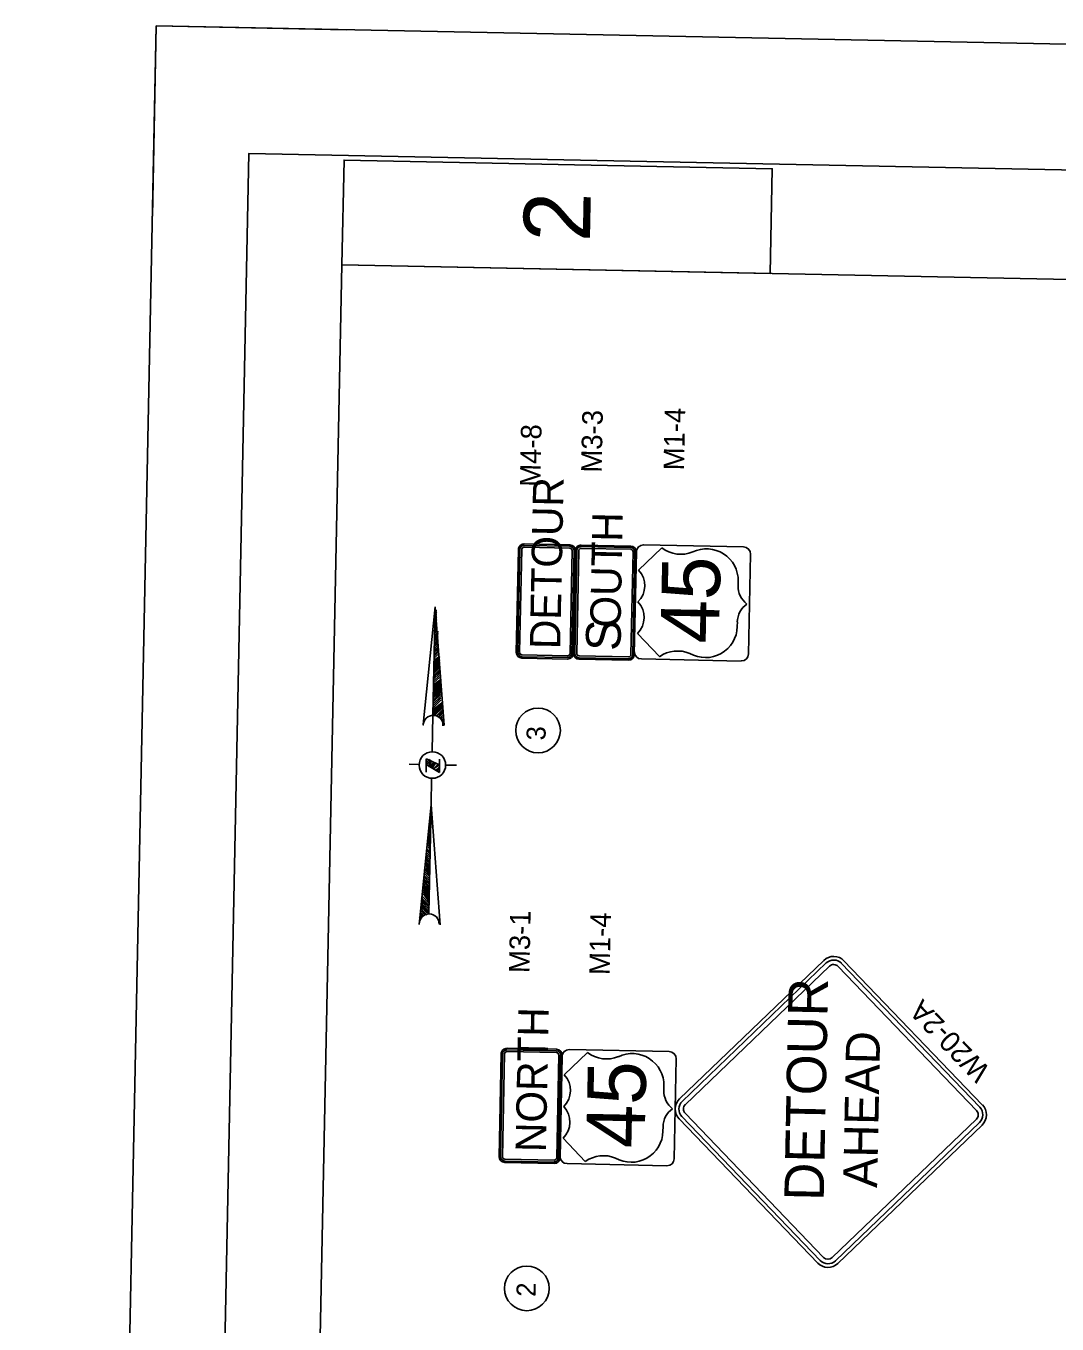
# Model space of a CAD drawing. Extents: x 311409 to 379449, y 121539 to 224848.
# Drawn here: x 311409 to 327657, y 204381 to 224848 of the extents above; entities that cross this region are included whole.
import ezdxf

# ---------------------------------------------------------------- set-up
doc = ezdxf.new("R2010")
doc.units = 0
for name, color, linetype in [('CA-TBLK', 7, 'Continuous'), ('CA-TEXT', 7, 'Continuous'), ('P_RDWY_Text', 7, 'Continuous'), ('P_SGN_Cell', 7, 'Continuous'), ('PLT_Sheet_Border', 7, 'Continuous'), ('PLT_Sheet_Info', 7, 'Continuous')]:
    doc.layers.add(name, color=color, linetype=linetype)

msp = doc.modelspace()

# ---------------------------------------------------------------- linework, layer by layer
at = {"layer": 'CA-TBLK'}
for p, q in [((317669, 213832), (317856, 215689)), ((317822, 213979), (317856, 215689)), ((317883, 215538), (317853, 215539)), ((317853, 215509), (317883, 215538)), ((317854, 215599), (317884, 215598)), ((317884, 215598), (317854, 215569)), ((317854, 215569), (317884, 215568)), ((317855, 215629), (317885, 215628)), ((317885, 215628), (317855, 215629)), ((317999, 213826), (317856, 215689)), ((317856, 215689), (317856, 215689)), ((317856, 215689), (317856, 215689)), ((317856, 215659), (317856, 215659)), ((317848, 215299), (317879, 215328)), ((317879, 215328), (317848, 215299)), ((317849, 215329), (317880, 215358)), ((317881, 215418), (317850, 215389)), ((317880, 215388), (317850, 215359)), ((317850, 215359), (317880, 215388)), ((317882, 215478), (317851, 215449)), ((317851, 215449), (317881, 215448)), ((317881, 215448), (317851, 215419)), ((317851, 215419), (317881, 215418)), ((317852, 215479), (317883, 215508)), ((317883, 215508), (317853, 215509)), ((317844, 215089), (317905, 215148)), ((317905, 215118), (317844, 215089)), ((317844, 215059), (317905, 215118)), ((317907, 215208), (317845, 215149)), ((317845, 215119), (317906, 215178)), ((317905, 215148), (317845, 215119)), ((317907, 215238), (317846, 215179)), ((317846, 215179), (317907, 215208)), ((317847, 215239), (317908, 215298)), ((317908, 215268), (317847, 215239)), ((317847, 215209), (317907, 215238)), ((317878, 215298), (317848, 215269)), ((317931, 214907), (317839, 214819)), ((317839, 214849), (317931, 214907)), ((317901, 214938), (317840, 214879)), ((317840, 214879), (317901, 214938)), ((317902, 214998), (317841, 214939)), ((317841, 214939), (317902, 214998)), ((317902, 214968), (317841, 214909)), ((317842, 214999), (317904, 215058)), ((317842, 214969), (317903, 215028)), ((317903, 215028), (317842, 214999)), ((317904, 215088), (317843, 215029)), ((317927, 214727), (317835, 214639)), ((317835, 214609), (317926, 214697)), ((317836, 214699), (317928, 214757)), ((317928, 214757), (317836, 214669)), ((317836, 214669), (317927, 214727)), ((317837, 214729), (317929, 214817)), ((317928, 214787), (317837, 214729)), ((317838, 214759), (317929, 214847)), ((317929, 214847), (317838, 214789)), ((317929, 214817), (317838, 214759)), ((317839, 214819), (317930, 214877)), ((317830, 214399), (317952, 214487)), ((317952, 214487), (317830, 214399)), ((317953, 214547), (317831, 214429)), ((317831, 214429), (317953, 214517)), ((317924, 214577), (317832, 214489)), ((317832, 214489), (317924, 214577)), ((317832, 214459), (317953, 214547)), ((317833, 214549), (317925, 214637)), ((317925, 214637), (317833, 214549)), ((317925, 214607), (317833, 214519)), ((317834, 214579), (317926, 214667)), ((317926, 214667), (317835, 214609)), ((317826, 214189), (317948, 214307)), ((317950, 214367), (317827, 214249)), ((317827, 214219), (317949, 214337)), ((317948, 214307), (317827, 214219)), ((317950, 214397), (317828, 214279)), ((317828, 214279), (317950, 214367)), ((317829, 214339), (317951, 214457)), ((317951, 214427), (317829, 214339)), ((317829, 214309), (317950, 214397)), ((317951, 214457), (317830, 214369)), ((317822, 214009), (317975, 214126)), ((317975, 214126), (317822, 214009)), ((317974, 214096), (317822, 213979)), ((317976, 214186), (317823, 214039)), ((317823, 214039), (317975, 214156)), ((317947, 214217), (317824, 214099)), ((317824, 214099), (317947, 214217)), ((317824, 214069), (317976, 214186)), ((317825, 214159), (317948, 214277)), ((317948, 214277), (317825, 214159)), ((317947, 214247), (317825, 214129)), ((317852, 213979), (317974, 214096)), ((317822, 213979), (317810, 213409)), ((317974, 214066), (317882, 213978)), ((317882, 213978), (317973, 214036)), ((317973, 214036), (317911, 213947)), ((317972, 214006), (317911, 213947)), ((317911, 213947), (317972, 214006)), ((317941, 213947), (317972, 213976)), ((317971, 213946), (317941, 213917)), ((317941, 213917), (317971, 213946)), ((317970, 213886), (317971, 213916)), ((317970, 213886), (317970, 213886)), ((317971, 213916), (317971, 213916)), ((317969, 213856), (317969, 213856)), ((317969, 213856), (317969, 213856)), ((317969, 213826), (317999, 213826)), ((317718, 213291), (317714, 213081)), ((317777, 213260), (317716, 213201)), ((317716, 213201), (317777, 213260)), ((317716, 213201), (317807, 213259)), ((317717, 213261), (317748, 213291)), ((317748, 213291), (317717, 213261)), ((317778, 213290), (317717, 213231)), ((317718, 213291), (317718, 213291)), ((317926, 213197), (317718, 213291)), ((317807, 213259), (317746, 213171)), ((317928, 213287), (317924, 213077)), ((317596, 213204), (317446, 213207)), ((317716, 213201), (317924, 213077)), ((317746, 213171), (317837, 213229)), ((317837, 213229), (317776, 213170)), ((317776, 213170), (317867, 213228)), ((317805, 213139), (317867, 213228)), ((317867, 213228), (317806, 213169)), ((317835, 213139), (317896, 213198)), ((317896, 213198), (317835, 213139)), ((317926, 213197), (317835, 213139)), ((317864, 213108), (317926, 213167)), ((317926, 213167), (317864, 213108)), ((317894, 213108), (317925, 213137)), ((317925, 213137), (317894, 213108)), ((317924, 213077), (317924, 213107)), ((318016, 213195), (318196, 213191)), ((317802, 212989), (317793, 212569)), ((317605, 210683), (317793, 212569)), ((317759, 210860), (317793, 212569)), ((317790, 212419), (317791, 212449)), ((317791, 212449), (317791, 212449)), ((317792, 212509), (317792, 212509)), ((317792, 212479), (317792, 212479)), ((317792, 212479), (317792, 212479)), ((317935, 210676), (317793, 212569)), ((317793, 212569), (317793, 212569)), ((317793, 212539), (317793, 212539)), ((317793, 212539), (317793, 212539)), ((317757, 212240), (317786, 212210)), ((317787, 212270), (317788, 212300)), ((317787, 212270), (317787, 212240)), ((317787, 212240), (317787, 212270)), ((317788, 212300), (317789, 212330)), ((317788, 212300), (317788, 212300)), ((317790, 212389), (317789, 212360)), ((317789, 212360), (317789, 212330)), ((317789, 212360), (317789, 212360)), ((317790, 212419), (317790, 212419)), ((317790, 212389), (317790, 212389)), ((317753, 212060), (317783, 212030)), ((317784, 212090), (317754, 212120)), ((317754, 212120), (317784, 212090)), ((317783, 212030), (317754, 212090)), ((317754, 212090), (317783, 212060)), ((317784, 212120), (317755, 212150)), ((317786, 212210), (317756, 212210)), ((317756, 212210), (317786, 212180)), ((317756, 212180), (317784, 212120)), ((317785, 212150), (317756, 212180)), ((317719, 211851), (317778, 211790)), ((317778, 211820), (317719, 211851)), ((317720, 211881), (317778, 211820)), ((317779, 211850), (317750, 211910)), ((317750, 211910), (317779, 211850)), ((317751, 211970), (317780, 211910)), ((317780, 211910), (317751, 211970)), ((317780, 211880), (317751, 211940)), ((317752, 212000), (317781, 211940)), ((317781, 211970), (317752, 212000)), ((317753, 212030), (317781, 211970)), ((317782, 212000), (317753, 212030)), ((317715, 211671), (317774, 211580)), ((317774, 211610), (317715, 211671)), ((317774, 211580), (317715, 211641)), ((317715, 211641), (317773, 211550)), ((317716, 211701), (317775, 211640)), ((317776, 211700), (317717, 211761)), ((317717, 211761), (317776, 211700)), ((317775, 211640), (317717, 211731)), ((317717, 211731), (317775, 211670)), ((317718, 211821), (317777, 211760)), ((317777, 211760), (317718, 211821)), ((317777, 211730), (317718, 211791)), ((317681, 211461), (317769, 211370)), ((317769, 211370), (317681, 211461)), ((317769, 211340), (317681, 211432)), ((317682, 211521), (317771, 211430)), ((317682, 211491), (317770, 211400)), ((317770, 211400), (317682, 211491)), ((317771, 211460), (317683, 211551)), ((317713, 211551), (317771, 211460)), ((317772, 211520), (317714, 211611)), ((317772, 211490), (317714, 211581)), ((317714, 211581), (317772, 211520)), ((317764, 211100), (317676, 211222)), ((317676, 211222), (317765, 211130)), ((317765, 211130), (317677, 211252)), ((317678, 211312), (317766, 211190)), ((317766, 211220), (317678, 211312)), ((317678, 211282), (317765, 211160)), ((317766, 211190), (317678, 211282)), ((317767, 211250), (317679, 211372)), ((317679, 211372), (317768, 211280)), ((317679, 211342), (317767, 211250)), ((317680, 211402), (317768, 211310)), ((317768, 211310), (317680, 211402)), ((317759, 210860), (317642, 211012)), ((317642, 211012), (317760, 210890)), ((317761, 210950), (317643, 211072)), ((317760, 210920), (317643, 211042)), ((317643, 211042), (317760, 210920)), ((317644, 211102), (317761, 210950)), ((317761, 210980), (317644, 211102)), ((317645, 211132), (317762, 211010)), ((317762, 211010), (317645, 211132)), ((317675, 211162), (317763, 211040)), ((317763, 211070), (317676, 211192)), ((317676, 211192), (317763, 211070)), ((317608, 210803), (317637, 210772)), ((317638, 210832), (317668, 210802)), ((317638, 210802), (317638, 210832)), ((317668, 210802), (317639, 210862)), ((317639, 210862), (317668, 210832)), ((317640, 210922), (317698, 210831)), ((317728, 210830), (317640, 210922)), ((317698, 210831), (317640, 210892)), ((317641, 210952), (317729, 210860)), ((317759, 210860), (317641, 210952)), ((317642, 210982), (317759, 210860)), ((317606, 210713), (317606, 210713)), ((317607, 210773), (317637, 210772)), ((317637, 210772), (317607, 210773)), ((317607, 210743), (317607, 210743)), ((317607, 210743), (317607, 210743))]:
    msp.add_line(p, q, dxfattribs=at)
msp.add_circle((317813, 213195), 209, dxfattribs=at)
for centre, start, end in [((317826, 213821), 358.8468, 178.8468), ((317826, 213821), 178.84682431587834, 178.8468298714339), ((317763, 210691), 358.8468, 178.8468), ((317763, 210691), 358.84700764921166, 358.8470132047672)]:
    msp.add_arc(centre, 157, start, end, dxfattribs=at)
at = {"layer": 'CA-TEXT'}
for centre in [(319479, 213740), (319302, 204944)]:
    msp.add_circle(centre, 352, dxfattribs=at)
at = {"layer": 'P_RDWY_Text'}
msp.add_lwpolyline([(311409, 122868), (313463, 224848), (379449, 223519), (377396, 121539)], close=True, dxfattribs=at)
at = {"layer": 'P_SGN_Cell'}
for p, q in [((320036, 214955), (320068, 216576)), ((320058, 214955), (320091, 216575)), ((320088, 214955), (320121, 216574)), ((320159, 216611), (320939, 216596)), ((320160, 216664), (320940, 216648)), ((320160, 216641), (320940, 216626)), ((320976, 216557), (320943, 214938)), ((321006, 216557), (320973, 214937)), ((321028, 216556), (320996, 214937)), ((320996, 214982), (321028, 216556)), ((321429, 216618), (321064, 216268)), ((321143, 216666), (322718, 216635)), ((322828, 216520), (322812, 215733)), ((322828, 216520), (322828, 216520)), ((322631, 216022), (322633, 216093)), ((322812, 215733), (322796, 214945)), ((322618, 215379), (322620, 215451)), ((321044, 215268), (321394, 214904)), ((320125, 214917), (320905, 214901)), ((320124, 214887), (320904, 214871)), ((320124, 214864), (320904, 214848)), ((322681, 214835), (321107, 214867)), ((318865, 207020), (318898, 208641)), ((318888, 207021), (318920, 208640)), ((318918, 207020), (318950, 208640)), ((318989, 208706), (319769, 208691)), ((318989, 208676), (319768, 208661)), ((318990, 208729), (319770, 208713)), ((319805, 208622), (319773, 207003)), ((319835, 208622), (319803, 207002)), ((319858, 208621), (319825, 207002)), ((319826, 207024), (319857, 208599)), ((320258, 208661), (319893, 208311)), ((319972, 208709), (321547, 208677)), ((321657, 208563), (321641, 207775)), ((321657, 208563), (321657, 208563)), ((321460, 208065), (321462, 208136)), ((321641, 207775), (321625, 206988)), ((321447, 207422), (321449, 207493)), ((319873, 207311), (320223, 206946)), ((318953, 206929), (319733, 206914)), ((318954, 206982), (319734, 206966)), ((318954, 206952), (319734, 206936)), ((321510, 206878), (319936, 206910))]:
    msp.add_line(p, q, dxfattribs=at)
for points in [[(319169, 216592), (319136, 214973)], [(319191, 216592), (319158, 214972)], [(319221, 216591), (319188, 214972)], [(319979, 216614), (319259, 216628)], [(319980, 216666), (319260, 216681)], [(319980, 216644), (319260, 216658)], [(319983, 214956), (320016, 216575)], [(320013, 214955), (320046, 216575)], [(320036, 214955), (320068, 216574)], [(319225, 214933), (319945, 214919)], [(319225, 214903), (319944, 214889)], [(319224, 214881), (319944, 214866)], [(323982, 210115), (321710, 207933)], [(324021, 210074), (321750, 207892)], [(324071, 210022), (321799, 207840)], [(326388, 207750), (324206, 210021)], [(326439, 207799), (324258, 210070)], [(326480, 207839), (324299, 210110)], [(321704, 207615), (323886, 205343)], [(321745, 207655), (323927, 205383)], [(321796, 207704), (323978, 205432)], [(324115, 205430), (326387, 207612)], [(324164, 205378), (326436, 207560)], [(324204, 205337), (326476, 207519)]]:
    msp.add_lwpolyline(points, dxfattribs=at)
for centre, radius, start, end in [((319259, 216591), 90, 88.8468, 178.8468), ((319259, 216591), 67.5, 88.8468, 178.8468), ((319259, 216591), 37.5, 88.8468, 178.8468), ((319978, 216576), 37.5, 358.8468, 88.8468), ((319978, 216576), 90, 358.8468, 88.8468), ((319978, 216576), 67.5, 358.8468, 88.8468), ((320158, 216574), 90, 88.8462, 178.8462), ((320158, 216574), 67.5, 88.8462, 178.8462), ((320158, 216574), 37.5, 88.8462, 178.8462), ((320938, 216558), 37.5, 358.8462, 88.8462), ((320938, 216558), 90, 358.8462, 88.8462), ((320938, 216558), 67.5, 358.8462, 88.8462), ((321141, 216554), 112, 88.8462, 178.8462), ((321729, 217018), 500, 233.1143, 291.9873), ((322133, 216104), 500, 358.8462, 115.6928), ((322715, 216522), 112, 358.8462, 88.8462), ((320804, 216023), 357, 314.4191, 43.2734), ((322993, 216017), 362, 179.1885, 231.634), ((320794, 215523), 357, 314.4191, 43.2734), ((322981, 215441), 362, 126.0584, 178.5039), ((322118, 215389), 500, 240.0981, 358.8463), ((319226, 214971), 90, 178.8468, 268.8468), ((319226, 214971), 67.5, 178.8468, 268.8468), ((319226, 214971), 37.5, 178.8468, 268.8468), ((319226, 214971), 37.5, 178.8468, 186.1883), ((319946, 214956), 90, 268.8468, 358.8468), ((319946, 214956), 67.5, 268.8468, 358.8468), ((319946, 214956), 37.5, 268.8468, 358.8468), ((320126, 214954), 90, 179.6119, 268.8462), ((320126, 214954), 67.5, 178.8462, 268.8462), ((320126, 214954), 37.5, 178.8462, 268.8462), ((320906, 214938), 67.5, 268.8462, 358.8462), ((320906, 214938), 90, 268.8462, 358.8462), ((320906, 214938), 37.5, 268.8462, 358.8462), ((321109, 214979), 112, 178.8462, 268.8462), ((321679, 214493), 500, 67.7159, 124.7982), ((322684, 214948), 112, 268.8462, 358.8462), ((324138, 209953), 225, 43.8468, 133.8468), ((324138, 209953), 168, 43.8468, 133.8468), ((324138, 209953), 96.4, 43.8468, 133.8468), ((318988, 208639), 90, 88.8462, 178.8462), ((318988, 208639), 67.5, 88.8462, 178.8462), ((318988, 208639), 37.5, 88.8462, 178.8462), ((319768, 208623), 37.5, 358.8462, 88.8462), ((319768, 208623), 67.5, 358.8462, 88.8462), ((319768, 208623), 90, 358.8462, 88.8462), ((319970, 208597), 112, 88.8462, 178.8462), ((320558, 209061), 500, 233.1143, 291.9873), ((320962, 208146), 500, 358.8462, 115.6928), ((321544, 208565), 112, 358.8462, 88.8462), ((319633, 208066), 357, 314.4191, 43.2734), ((321822, 208060), 362, 179.1885, 231.634), ((319623, 207566), 357, 314.4191, 43.2734), ((321810, 207484), 362, 126.0584, 178.5039), ((321866, 207771), 225, 133.8449, 223.8468), ((321866, 207771), 168, 133.8449, 223.8468), ((321866, 207771), 96.4, 133.8449, 223.8468), ((326320, 207681), 96.4, 313.854, 44.4977), ((326320, 207681), 168, 313.854, 44.4977), ((326320, 207681), 225, 313.854, 44.4977), ((320947, 207432), 500, 240.0981, 358.8463), ((318955, 207019), 90, 179.6119, 268.8462), ((318955, 207019), 67.5, 178.8462, 268.8462), ((318955, 207019), 37.5, 178.8462, 268.8462), ((319735, 207004), 90, 268.8462, 358.8462), ((319735, 207004), 37.5, 268.8462, 358.8462), ((319735, 207004), 67.5, 268.8462, 358.8462), ((319938, 207022), 112, 178.8462, 268.8462), ((320509, 206536), 500, 67.7159, 124.7982), ((321513, 206990), 112, 268.8462, 358.8462), ((324048, 205499), 225, 223.8468, 313.8468), ((324048, 205499), 168, 223.8468, 313.8468), ((324048, 205499), 96.4, 223.8468, 313.8468)]:
    msp.add_arc(centre, radius, start, end, dxfattribs=at)
at = {"layer": 'PLT_Sheet_Border'}
for points in [[(377396, 121539), (379449, 223519), (313463, 224848), (311409, 122868)], [(375910, 122290), (377910, 221569), (314923, 222838), (312923, 123558)]]:
    msp.add_lwpolyline(points, close=True, dxfattribs=at)
at = {"layer": 'PLT_Sheet_Info'}
for p, q in [((313402, 221848), (313463, 224848)), ((316462, 224787), (313463, 224848)), ((314485, 126602), (316388, 221083)), ((376375, 219875), (316388, 221083))]:
    msp.add_line(p, q, dxfattribs=at)
msp.add_lwpolyline([(316388, 221083), (316421, 222733), (323169, 222597), (323136, 220947)], close=True, dxfattribs=at)

# ---------------------------------------------------------------- texts
at = {"layer": 'CA-TEXT'}
for s, p in [('3', (319596, 213581)), ('2', (319438, 204809))]:
    msp.add_text(s, height=300, rotation=88.8468, dxfattribs=at).set_placement(p)
at = {"layer": 'P_SGN_Cell'}
for s, height, rotation, p in [('M1-4', 324, 88.8462, (321779, 217839)), ('M3-3', 324, 88.8462, (320481, 217803)), ('M4-8', 324, 88.8468, (319515, 217579)), ('DETOUR', 480, 88.8468, (319828, 215019)), ('OUTH', 480, 88.8462, (320779, 215358)), ('45', 920, 88.8462, (322328, 215106)), ('S', 549, 88.8462, (320778, 214991)), ('M3-1', 324, 88.8462, (319343, 209913)), ('M1-4', 324, 88.8462, (320608, 209882)), ('DETOUR', 621.4, 88.8468, (323980, 206320)), ('W20-2A', 324, 133.8468, (326623, 208390)), ('NORTH', 480, 88.8462, (319602, 207089)), ('AHEAD', 535.7, 88.8468, (324822, 206525)), ('45', 920, 88.8462, (321157, 207148))]:
    msp.add_text(s, height=height, rotation=rotation, dxfattribs=at).set_placement(p)
at = {"layer": 'PLT_Sheet_Info'}
msp.add_text('2', height=1050, rotation=88.8462, dxfattribs=at).set_placement((320296, 221437))

doc.saveas('drawing.dxf')
